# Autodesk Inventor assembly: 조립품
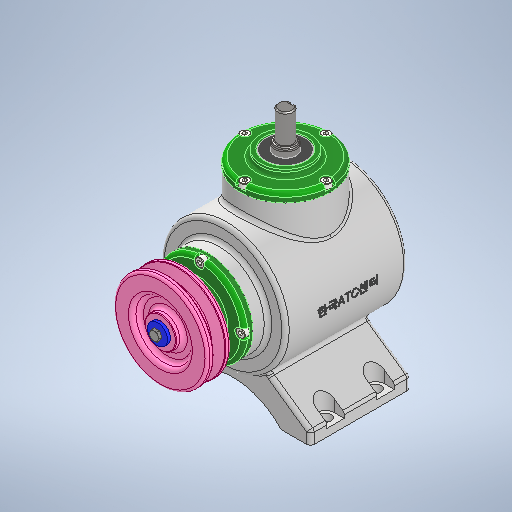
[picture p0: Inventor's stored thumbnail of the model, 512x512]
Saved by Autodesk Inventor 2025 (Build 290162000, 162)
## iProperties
Created: 2024-07
Part Number: 조립품
Document SubType Name: Assembly
Designer: admin
Author: admin
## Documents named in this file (15)
- C:\Users\admin\Desktop\740709V1010\조립품.iam
- C:\Users\admin\Desktop\740709V1010\본체.ipt
- C:\Users\admin\Desktop\오토캐드\20210615\공용부품_20240615_2\V-벨트풀리\V-벨트풀리.ipt
- C:\Users\admin\Desktop\오토캐드\20210615\공용부품_20240615_2\메인 베벨기어\메인 베벨기어.ipt
- C:\Users\admin\Desktop\오토캐드\20210615\공용부품_20240615_2\메인 축\메인 축.ipt
- C:\Users\admin\Desktop\오토캐드\20210615\공용부품_20240615_2\베어링 6203\베어링 6203.ipt
- C:\Users\admin\Desktop\오토캐드\20210615\공용부품_20240615_2\볼트 M4 x 10\볼트 M4 x 10.ipt
- C:\Users\admin\Desktop\오토캐드\20210615\공용부품_20240615_2\서브 베벨기어\서브 베벨기어.ipt
- C:\Users\admin\Desktop\오토캐드\20210615\공용부품_20240615_2\서브 축\서브 축.ipt
- C:\Users\admin\Desktop\오토캐드\20210615\공용부품_20240615_2\오일실 17 x 32 x 8\오일실 17 x 32 x 8.ipt
- C:\Users\admin\Desktop\오토캐드\20210615\공용부품_20240615_2\와셔 4 x 16\와셔 4 x 16.ipt
- C:\Users\admin\Desktop\오토캐드\20210615\공용부품_20240615_2\육각볼트 M4 x 8\육각볼트 M4 x 8.ipt
- C:\Users\admin\Desktop\오토캐드\20210615\공용부품_20240615_2\커버\커버.ipt
- C:\Users\admin\Desktop\오토캐드\20210615\공용부품_20240615_2\키 4 x 4 x 14\키 4 x 4 x 14.ipt
- C:\Users\admin\Desktop\오토캐드\20210615\공용부품_20240615_2\키 5 x 5 x 14\키 5 x 5 x 14.ipt
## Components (1 placed, 1 different names)
1. V-벨트풀리:1 — 각도:3
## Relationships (1: Angle 1)
- 각도:3 [Angle]: V-벨트풀리:1
